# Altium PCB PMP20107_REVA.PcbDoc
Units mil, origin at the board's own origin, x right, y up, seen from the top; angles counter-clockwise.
Board outline 1580 x 1300 mil, 4 copper layers (Top Layer, Signal Layer 1, Signal Layer 2, Bottom Layer), stack 61.2 mil thick; 70 components, 36 nets, 176 pads, 61 vias.
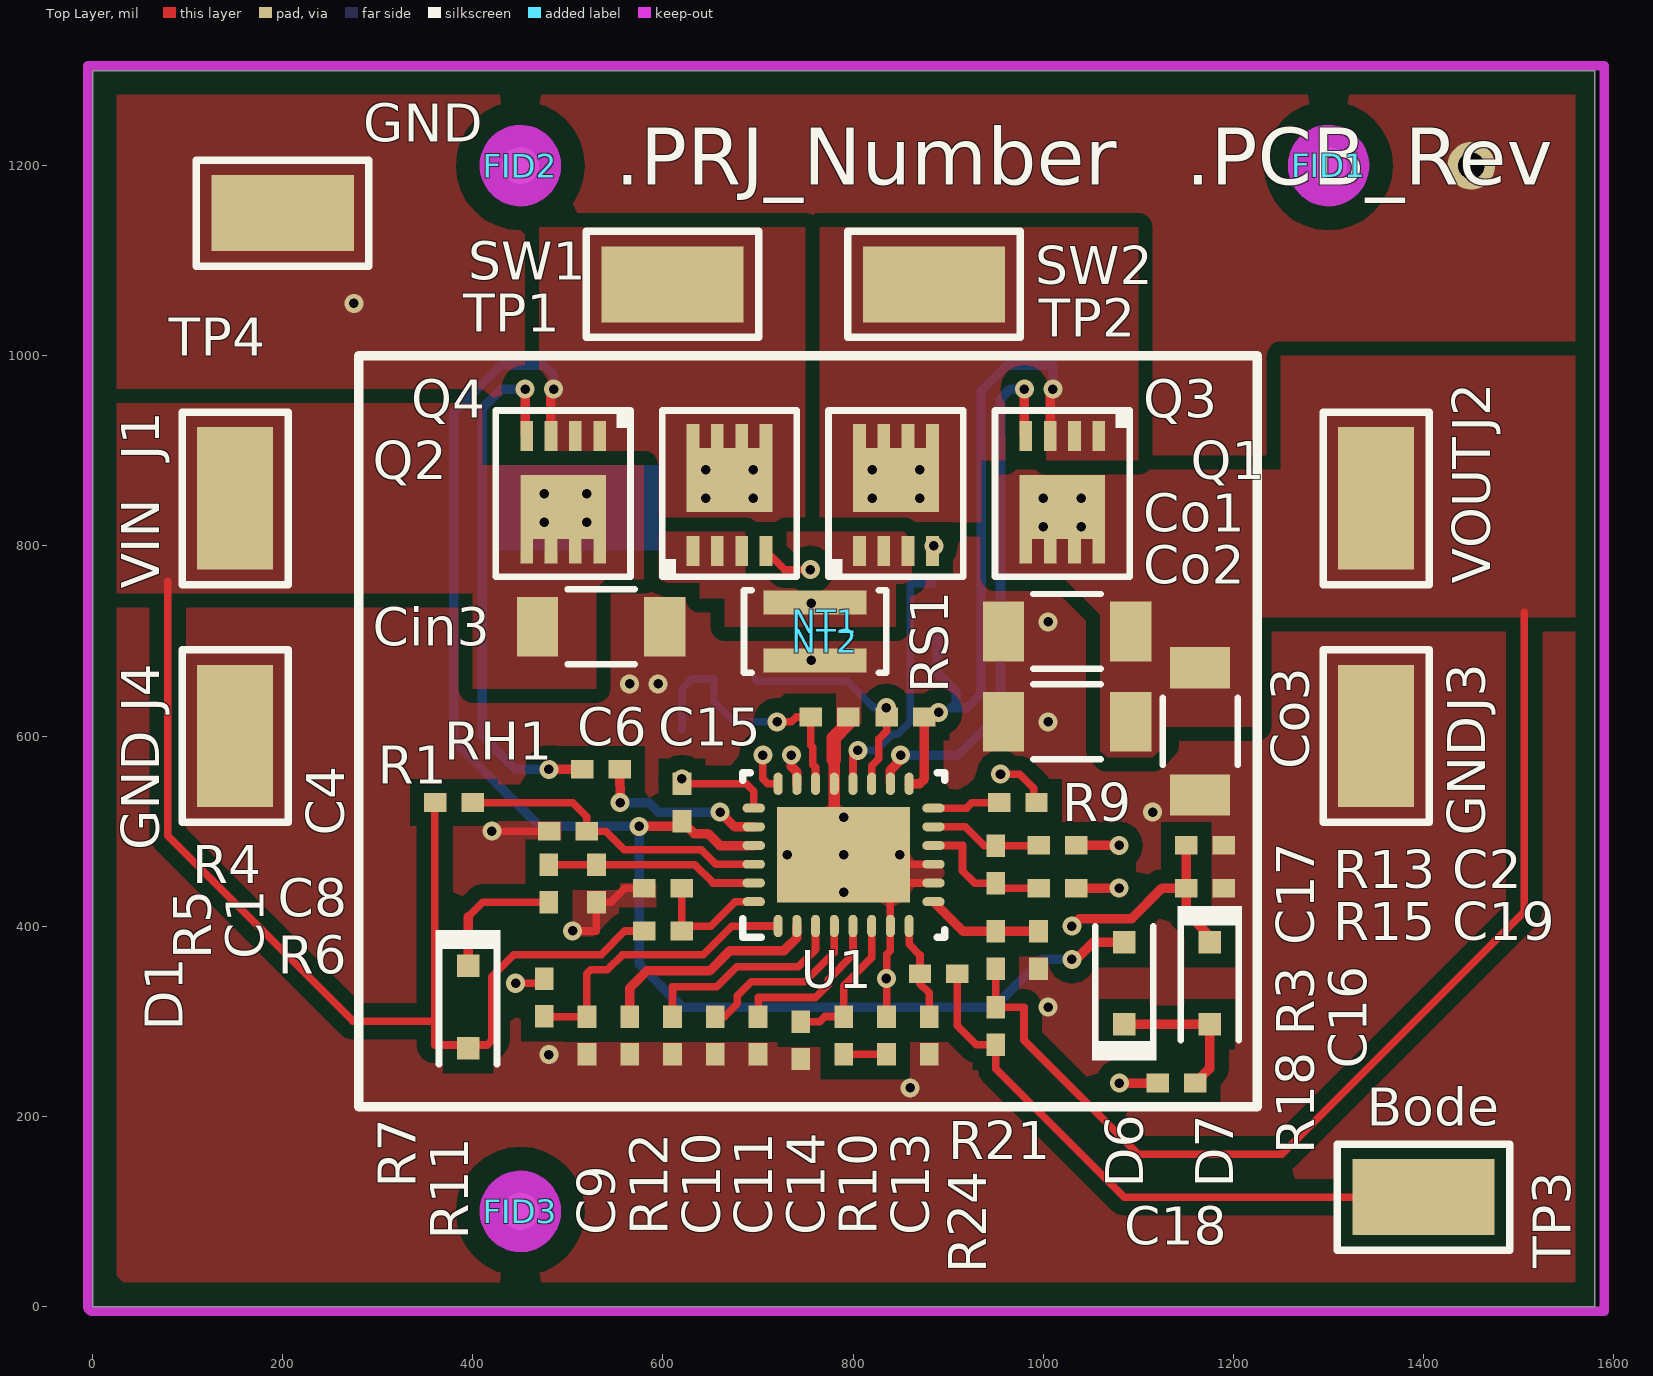
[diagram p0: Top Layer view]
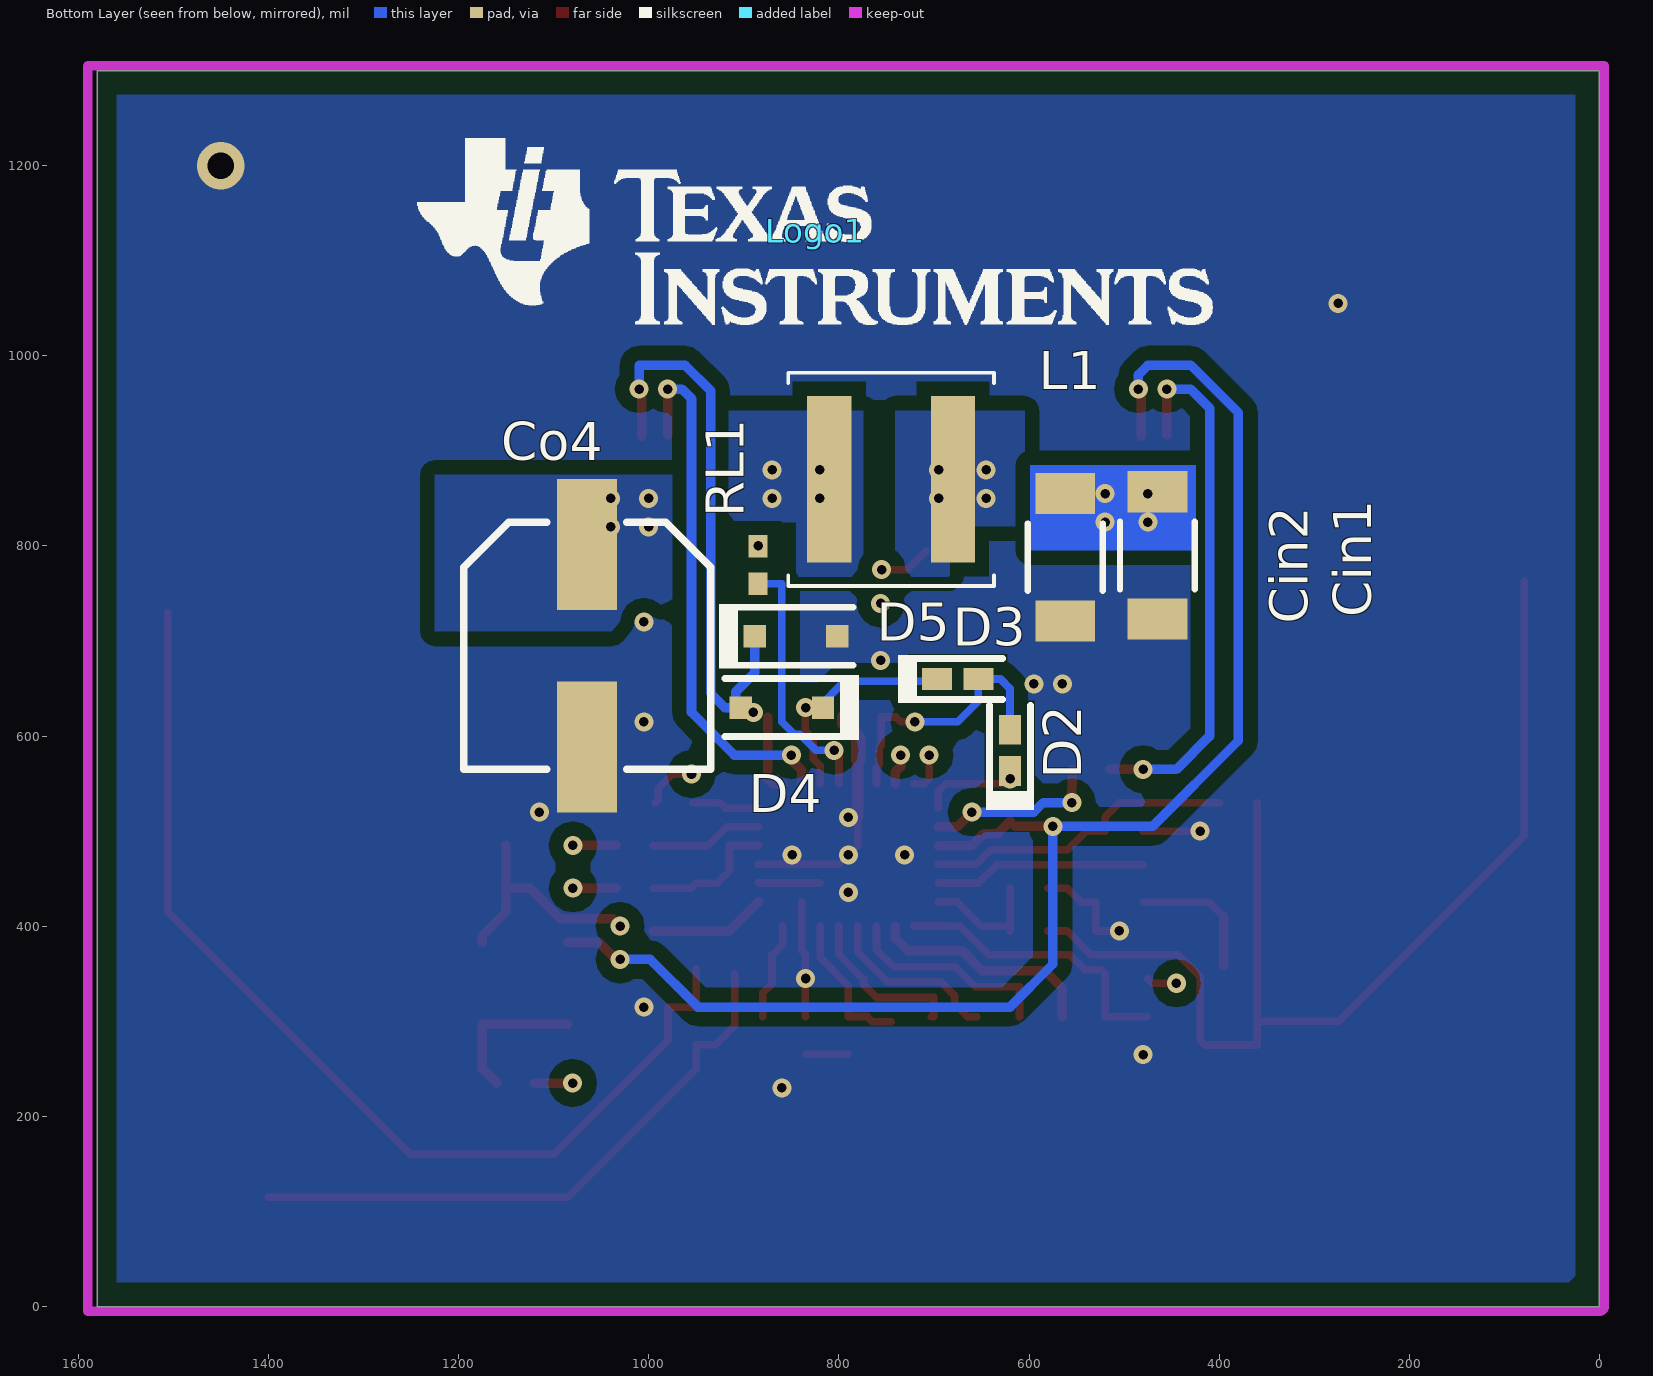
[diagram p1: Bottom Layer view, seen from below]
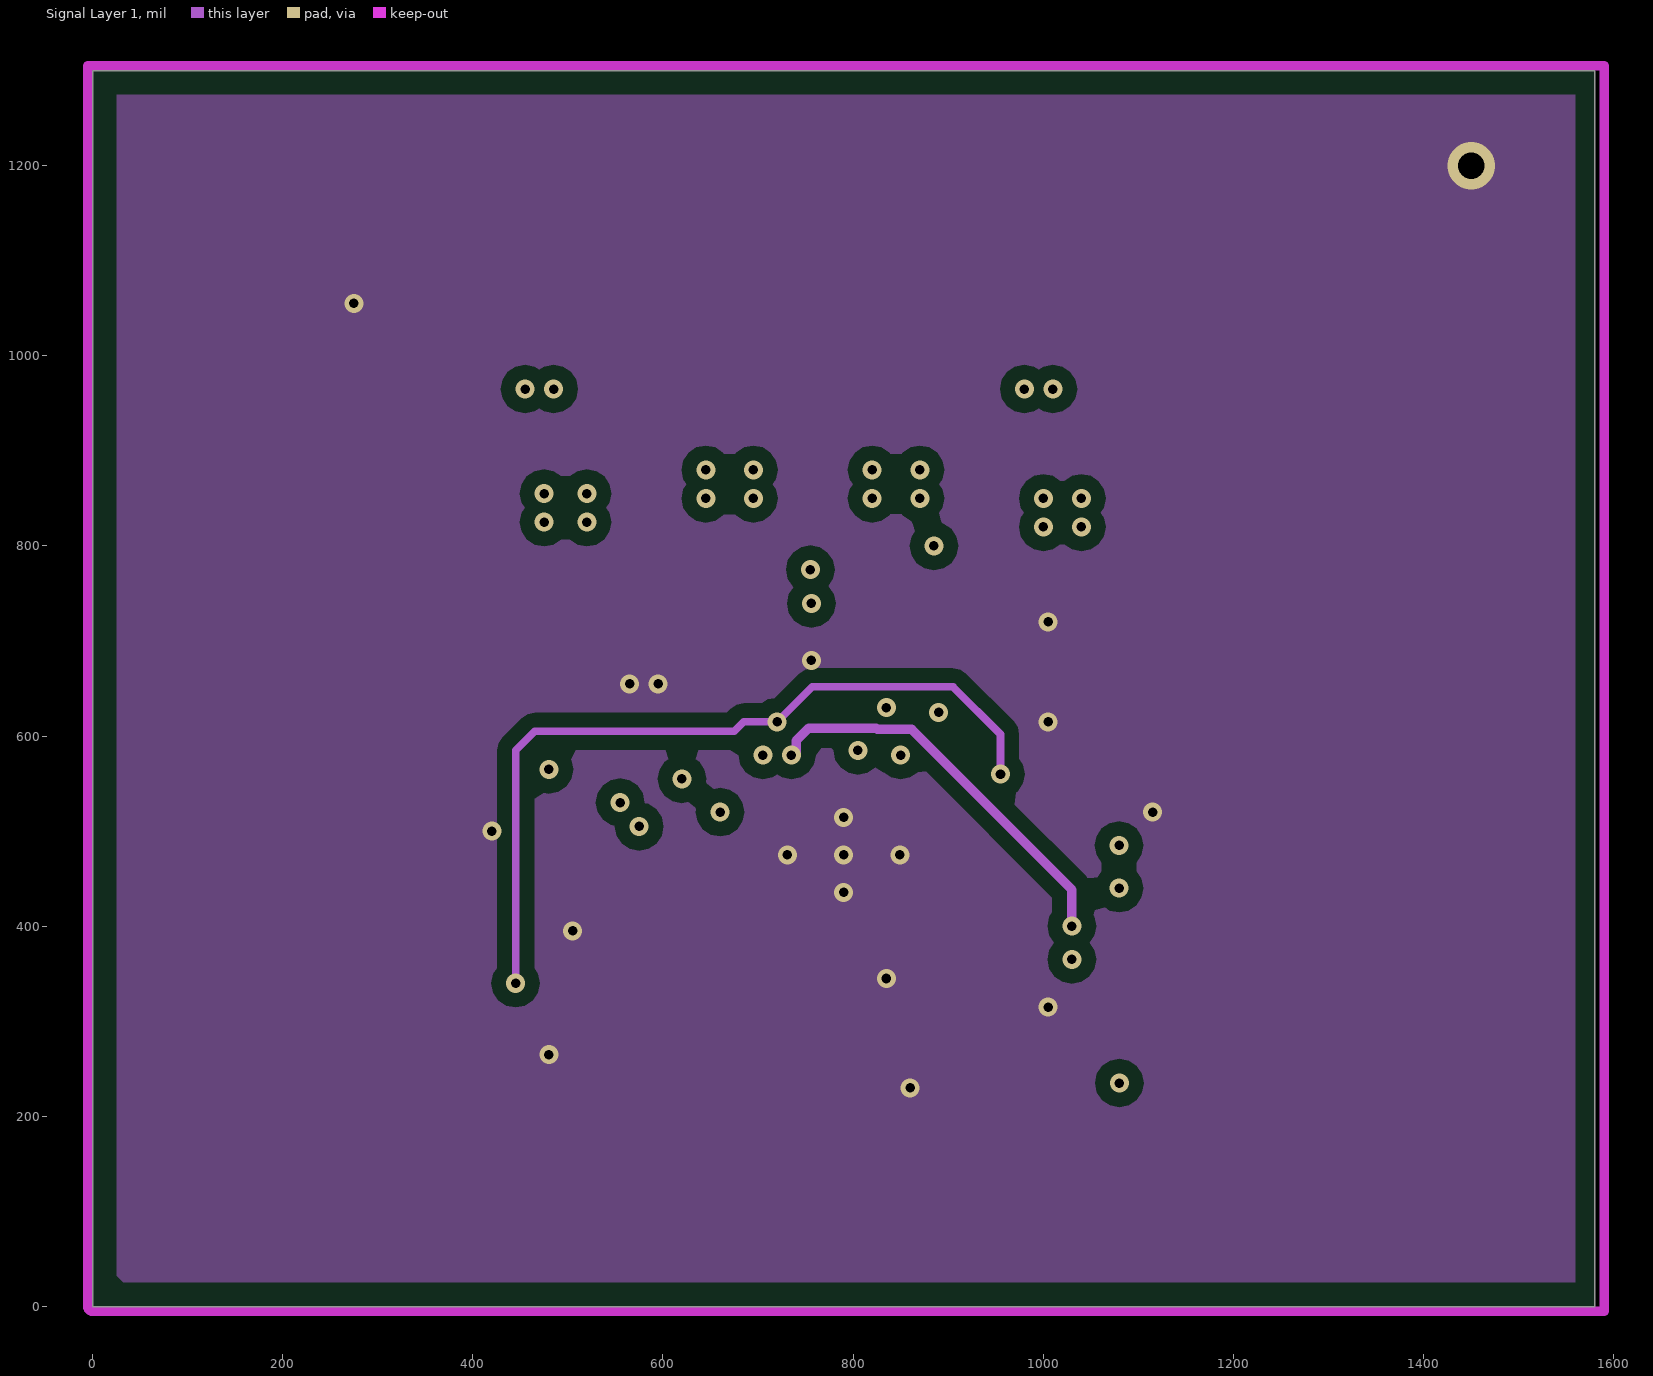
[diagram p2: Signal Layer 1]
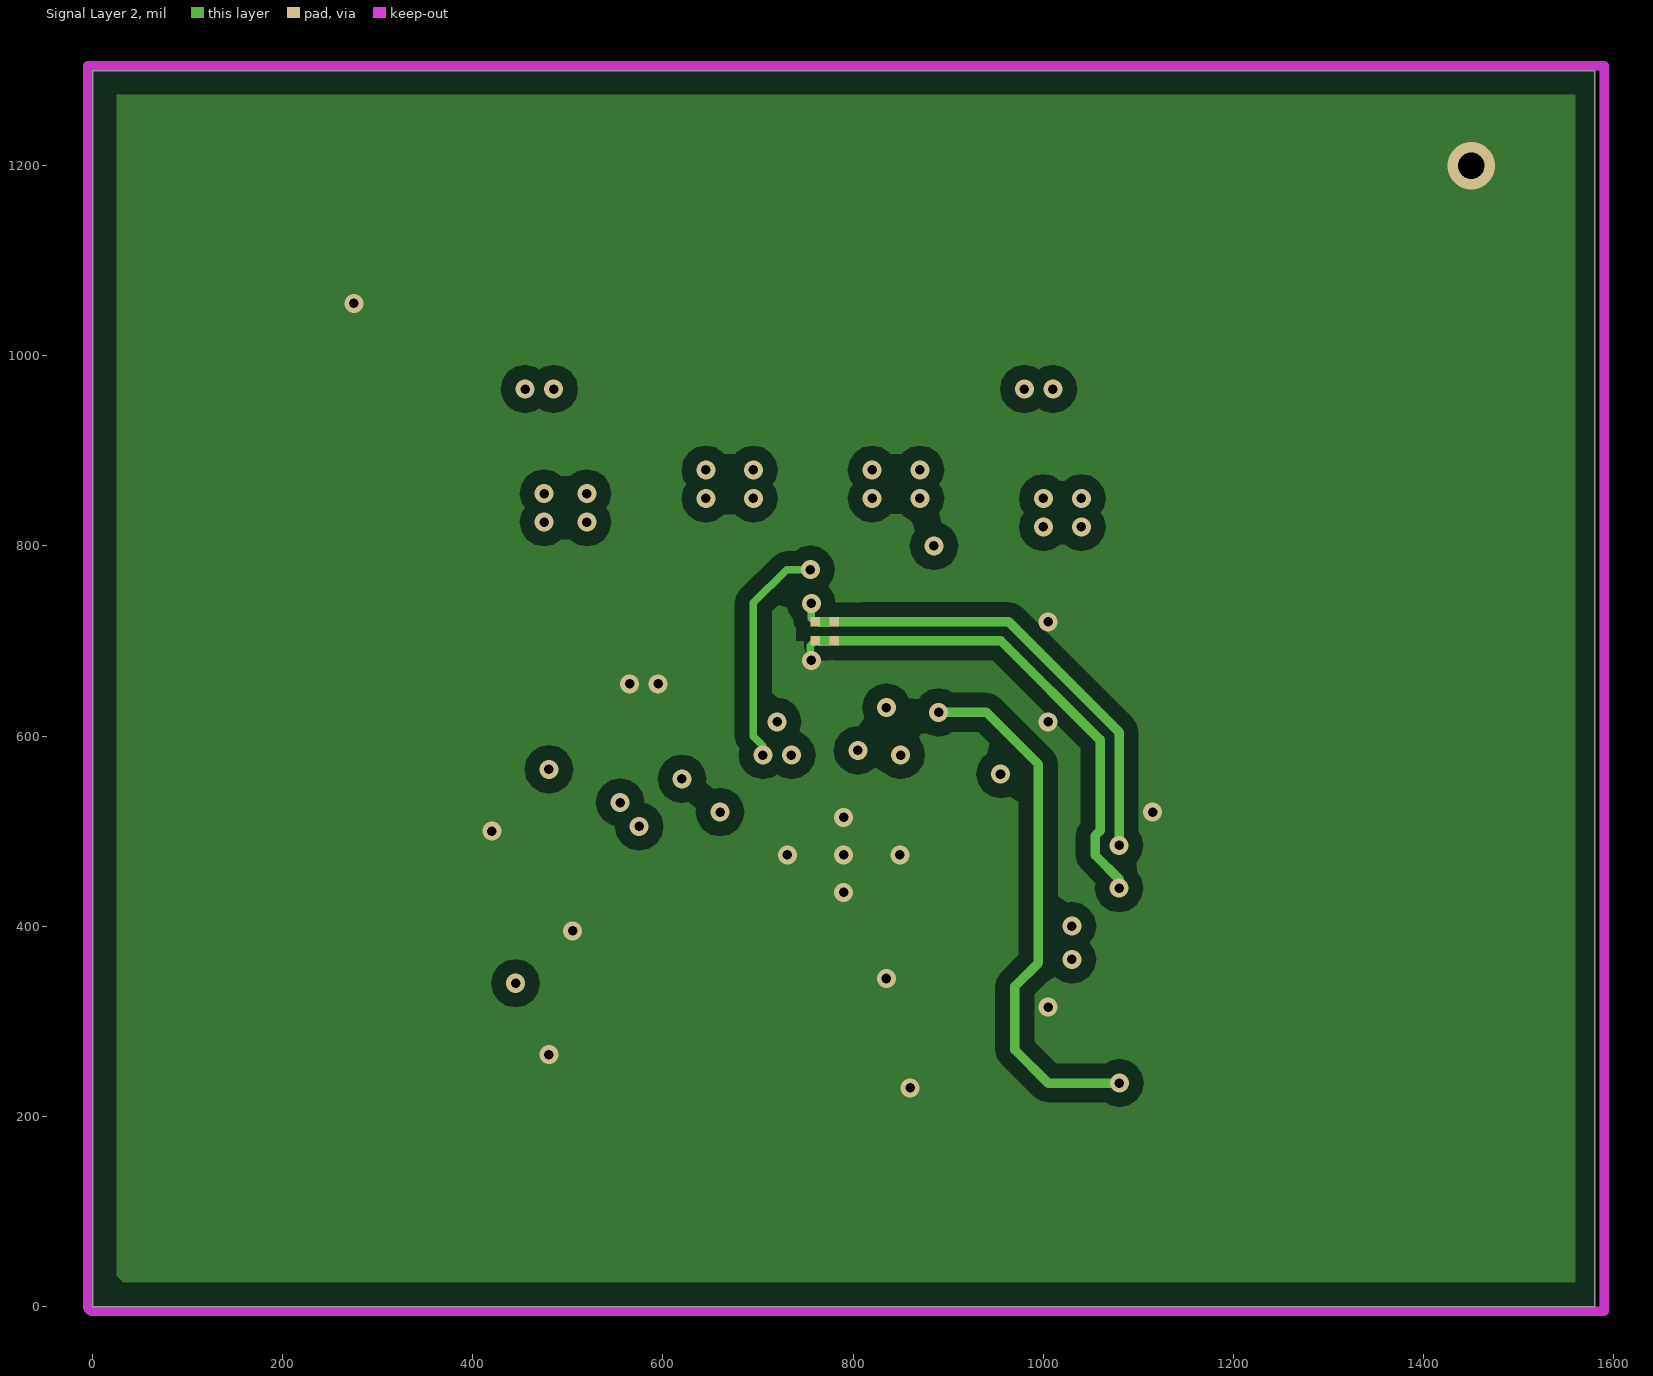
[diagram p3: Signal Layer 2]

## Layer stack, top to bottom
Top Solder: solder mask 0.4, Solder Resist, Dk 3.5
Top Layer: signal copper 1.4
Dielectric1: core 20, FR-4, Dk 4.8
Signal Layer 1: signal copper 0.7
Dielectric 2: prepreg 17, Dk 4.2
Signal Layer 2: signal copper 0.7
Dielectric 3: core 20, FR-4, Dk 4.8
Bottom Layer: signal copper 1.4
Bottom Solder: solder mask 0.4, Solder Resist, Dk 3.5

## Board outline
0,0 1580,0 1580,1300 0,1300

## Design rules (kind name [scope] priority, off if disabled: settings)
AcuteAngle [All] p1: minimum=4.50000000000000E+0001 checktracksonly=FALSE
AssemblyTestPointUsage [All] p1: valid=2
Clearance Clearance_Keepouts [((IsTrack Or IsArc) And Not InPoly) And IsFree and IsKeepOut vs ((IsTrack Or IsArc) And Not InPoly) And IsFree and IsKeepOut] p1: gap=0
Clearance Clearance_BoardEdge_MountingHoles [OnCopper and InComponentClass('Mounting Holes') vs IsKeepOut] p2: gap=40
Clearance Clearance_BoardEdge_Poly [OnCopper and InPoly vs IsKeepOut] p3: gap=25
Clearance Clearance_BoardEdge [OnCopper and Not InComponentClass('Logo') and not InComponentClass('FiducialMark') and not InRegion(1000,500,4000,800) and Not IsKeepout vs IsKeepOut] p4: gap=75
Clearance Clearance_Poly [InPolygon] p5: gap=15
Clearance [All] p6: gap=7.87
ComponentClearance ComponentClearance_Nettie [HasFootprint('Net-Tie_10mil')] p1: gap=0 collisioncheckmode=3 verticalgap=0 showdistances=FALSE
ComponentClearance ComponentClearance_MountingHoles_FiducialMarks [InComponentClass('Mounting Holes') vs InComponentClass('FiducialMark')] p2: gap=50 collisioncheckmode=3 verticalgap=10 showdistances=FALSE
ComponentClearance ComponentClearance_Shunt [InComponentClass('Header') vs InComponentClass('Shunt')] p3: gap=0 collisioncheckmode=3 verticalgap=0 showdistances=FALSE
ComponentClearance ComponentClearance_Logo [InComponentClass('Logo')] p4: gap=50 collisioncheckmode=3 verticalgap=10 showdistances=FALSE
ComponentClearance ComponentClearance_ScrewToNut [(HasFootprint('NY PMS 440 0025 PH')) vs (HasFootprint('Keystone_1902C'))] p5: gap=5 collisioncheckmode=3 verticalgap=10 showdistances=FALSE
ComponentClearance ComponentClearance_MountingHoles [InComponentClass('Mounting Holes')] p6: gap=250 collisioncheckmode=3 verticalgap=100000 showdistances=FALSE
ComponentClearance ComponentClearance_SmallPassives [HasFootprint('0201*') or HasFootprint('0402*') or HasFootprint('0508') or HasFootprint('0603*') or HasFootprint('0612') or HasFootprint('0805*') or HasFootprint('0815*') or HasFootprint('0830*') or HasFootprint('1206*') or HasFootprint('1210*') or HasFootprint('1808*') or HasFootprint('1812*') or HasFootprint('1825*') or HasFootprint('2010*') or HasFootprint('2220*') or HasFootprint('2225*') or HasFootprint('2512*') or HasFootprint('2728*') or HasFootprint('3518*') or HasFootprint('SOD-123') or HasFootprint('SOD-323') vs HasFootprint('0201*') or HasFootprint('0402*') or HasFootprint('0508') or HasFootprint('0603*') or HasFootprint('0612') or HasFootprint('0805*') or HasFootprint('0815*') or HasFootprint('0830*') or HasFootprint('1206*') or HasFootprint('1210*') or HasFootprint('1808*') or HasFootprint('1812*') or HasFootprint('1825*') or HasFootprint('2010*') or HasFootprint('2220*') or HasFootprint('2225*') or HasFootprint('2512*') or HasFootprint('2728*') or HasFootprint('3518*') or HasFootprint('SOD-123') or HasFootprint('SOD-323')] p7: gap=20 collisioncheckmode=3 verticalgap=10 showdistances=FALSE
ComponentClearance ComponentClearance_THtoSMT [IsThruComponent vs IsSMTComponent] p8: gap=100 collisioncheckmode=3 verticalgap=30 showdistances=FALSE
ComponentClearance ComponentClearance_THtoTH [IsThruComponent vs IsThruComponent] p9: gap=100 collisioncheckmode=3 verticalgap=30 showdistances=FALSE
ComponentClearance [All] p10: gap=20 collisioncheckmode=3 verticalgap=10 showdistances=FALSE
DiffPairsRouting [All] p1: maxlimit=100 minlimit=10 mostfreqgap=10 toplayer_minwidth=10 toplayer_maxwidth=15 toplayer_prefwidth=15 midlayer1_minwidth=10 midlayer1_maxwidth=15 midlayer1_prefwidth=15 midlayer2_minwidth=10 midlayer2_maxwidth=15 midlayer2_prefwidth=15 bottomlayer_minwidth=10 bottomlayer_maxwidth=15 bottomlayer_prefwidth=15 maxuncoupledlength=1000
FabricationTestPointUsage TestPointUsage [All] p1: valid=2 allowmultiple=FALSE
FabricationTestpoint Testpoint [All] p1: side=3 testpointundercomponent=TRUE minsize=40 maxsize=100 preferedsize=60 minholesize=0 maxholesize=40 preferedholesize=32 testpointgrid=1 allowsidetop=TRUE allowsidebottom=TRUE usegrid=TRUE gridtolerance=0.01
FanoutControl Fanout_LCC [IsLCC] p1: bgadir=Out bgaviamode=Centered fanoutstyle=Auto fanoutdirection=Alternating viagrid=1 // Fanout_LCC (Default Rule)
FanoutControl Fanout_BGA [IsBGA] p2: bgadir=Out bgaviamode=Centered fanoutstyle=Auto fanoutdirection=Alternating viagrid=1 // Fanout_BGA (Default Rule)
FanoutControl Fanout_Default [All] p4: bgadir=Out bgaviamode=Centered fanoutstyle=Auto fanoutdirection=Alternating viagrid=1 // Fanout_Default (Default Rule)
FanoutControl Fanout_Small [(CompPinCount < 5)] p5: bgadir=Out bgaviamode=Centered fanoutstyle=Auto fanoutdirection=OutThenIn viagrid=1 // Fanout_Small (Default Rule)
HoleSize [All] p1: absolutevalues=TRUE maxlimit=251 minlimit=8 maxpercent=80.000 minpercent=20.000
MinimumAnnularRing MinimumAnnularRing_ThermalPadVias [IsVia and InAnyComponent] p1: minimumring=5
MinimumAnnularRing [All] p2: minimumring=5
MinimumSolderMaskSliver MinimumSolderMaskSliver_Logo [InComponentClass('Logo') vs InComponentClass('Logo')] p1: minsoldermaskwidth=0.7
MinimumSolderMaskSliver [All] p2: minsoldermaskwidth=3.94
PlaneConnect [All] p1: planeconnectstyle=Direct reliefexpansion=10 reliefentries=4 reliefconductorwidth=10 reliefairgap=10
PolygonConnect [All] p1: connectstyle=Direct reliefconductorwidth=10 reliefentries=4 polygonreliefangle="90 Angle" airgapwidth=10
RoutingVias ThermalPadVias [IsVia and InAnyComponent] p1: holewidth=7.87 width=19.68 viastyle="Through Hole" minholewidth=7.87 minwidth=19.68 maxholewidth=12.99 maxwidth=23.62
RoutingVias [All] p2: holewidth=16 width=34 viastyle="Through Hole" minholewidth=7.87 minwidth=20 maxholewidth=40 maxwidth=65
SilkToBoardRegionClearance [Not ((IsComment or IsDesignator) And (Hide <> 'False')) and not InRegion(1000,500,4000,800)] p1:
SilkToSilkClearance SilkToSilkClearance_Pb-FreeLogo [(HasFootprint('Pb-Free_Overlay_Medium') OR HasFootprint('Pb-Free_Overlay_Small')) vs (HasFootprint('Pb-Free_Overlay_Medium') OR HasFootprint('Pb-Free_Overlay_Small'))] p1: silktosilkclearance=0
SilkToSilkClearance [All] p2: silktosilkclearance=4
SilkToSolderMaskClearance SilkToComonentPadClearance [IsPad and InAnycomponent] p1: minsilkscreentomaskgap=5 clearancetoexposedcopper=TRUE
SilkToSolderMaskClearance "Silk to Solder Mask Opening" [All] p2: minsilkscreentomaskgap=4 clearancetoexposedcopper=FALSE
SolderMaskExpansion [All] p1: expansion=1.97
UnpouredPolygon [All] p1: allowunpoured=FALSE
Width [All] p1: maxlimit=100 minlimit=6 preferedwidth=10 checkconnectedcopper=TRUE
14 further rules are at their usual default settings.

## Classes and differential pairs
component class PMP20107_REVA: C1 C2 C4 C6 C8 C9 C10 C11 C13 C14 C15 C16 C17 C18 C19 Cin1 Cin2 Cin3 Co1 Co2 Co3 Co4 Co6 D1 D2 D3 D4 D5 D6 D7 J1 J2 J3 J4 L1 NT1 NT2 Q1 Q2 Q3 Q4 R1 R3 R4 R6 R7 R9 R10 R11 R12 R13 R15 R18 R21 R24 RH1 RL1 RS1 TP1 TP2 TP3 TP4 U1
component class Logo: Logo1
component class PMP20107_REVA_Hardware: FID1 FID2 FID3 Logo1 ZZ1 ZZ2 ZZ3
component class FiducialMark: FID1 FID2 FID3
component class AssemblyNote: ZZ1 ZZ2 ZZ3
differential pair HDRV2: +HDRV2_P -HDRV2_N
differential pair HDRV1: +HDRV1_P -HDRV1_N
differential pair CS: +CS_P -CS_N

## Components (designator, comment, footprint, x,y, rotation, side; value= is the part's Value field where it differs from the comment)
C1 "GCM155R71H104KE02D" 0402L 530,445 r270 top
C2 "C1005X5R1E224M050BC" 0402L 1170,485 r0 top
C4 "GCM155R71H104KE02D" 0402L 620,530 r270 top
C6 "C1005X5R1C105K050BC" 0402L 775,620 r0 top
C8 "GCM155R71H104KE02D" 0402L 600,440 r0 top
C9 "CRCW04020000Z0ED" 0402L 565,285 r270 top
C10 "CC0402KRX7R9BB101" 0402L 655,285 r270 top
C11 "C1005X7R1H473K050BB" 0402L 700,285 r270 top
C13 "GRM155R71E473KA88D" 0402L 835,285 r90 top
C14 "GRM155R71E153KA61D" 0402L 745,280 r270 top
C15 "GCM155R71H104KE02D" 0402L 855,620 r180 top
C16 "C1005X5R1E224M050BC" 0402L 995,375 r270 top
C17 "C1005X7R1H221K" 0402L 950,465 r270 top
C18 "C1005X5R1E224M050BC" 0402L 1140,235 r180 top
C19 "GCM155R71H104KE02D" 0402L 1170,440 r0 top
Cin1 "C3216X7R1V106M160AC" 1206_190 465,790 r270 bottom
Cin2 "C3216X7R1V106M160AC" 1206_190 561.93,788.07 r270 bottom
Cin3 "C3216X7R1V106M160AC" 1206_190 535,715 r0 top
Co1 "GRM31CR71A226ME15L" 1206_190 1025,710 r180 top
Co2 "GRM31CR71A226ME15L" 1206_190 1025,615 r180 top
Co3 "GRM31CR71A226ME15L" 1206_190 1165,605 r270 top
Co4 "UUD1A101MCL1GS" SM_RADIAL_6.3AMM 1065,695 r270 bottom
D1 "BAT54HT1G" sod-323 395,315 r270 top
D2 "BAS516,115" SOD-523 620,585 r90 bottom
D3 "BAS516,115" SOD-523 675,660 r180 bottom
D4 "MMSZ5237BS-7-F" sod-323 860,630 r0 bottom
D5 "CUS05S40,H3F" sod-323 845,705 r180 bottom
D6 "CUS05S40,H3F" sod-323 1085,340 r90 top
D7 "CUS05S40,H3F" sod-323 1175,340 r270 top
FID1 "Fiducial" Fiducial10-20 1300,1200 r0 top
FID2 "Fiducial" Fiducial10-20 450,1200 r0 top
FID3 "Fiducial" Fiducial10-20 450,100 r0 top
J1 "VIN" Keystone_5019 150,850 r90 top
J2 "VOUT" Keystone_5019 1350,850 r90 top
J3 "GND" Keystone_5019 1350,600 r90 top
J4 "GND" Keystone_5019 150,600 r90 top
L1 "XAL5050-562MEB" XAL5050 745,870 r0 bottom
Logo1 "Texas Instruments" TI_Stacked_Overlay_Small 825,1130.71 r180 bottom
NT1 "Net-Tie" Net-Tie_10mil 770,720 r0 top net-tie
NT2 "Net-Tie" Net-Tie_10mil 770,700 r0 top net-tie
Q1 "BSZ097N04LS G" PG-TSDSON-8 1020,855 r270 top
Q2 "BSZ097N04LS G" PG-TSDSON-8 495,855 r270 top
Q3 "BSZ097N04LS G" PG-TSDSON-8 845,855 r90 top
Q4 "BSZ097N04LS G" PG-TSDSON-8 670,855 r90 top
R1 "CRCW040271K5FKED" 0402L 380,530 r180 top
R3 "CRCW040210R0JNED" 0402L 950,375 r270 top
R4 "CRCW040246K4FKED" 0402L 500,500 r0 top
R5 "CRCW040210R0JNED" 0402L 480,445 r270 top
R6 "CRCW040210R0JNED" 0402L 600,395 r0 top
R7 "CRCW04020000Z0ED" 0402L 475,325 r90 top
R9 "CRCW040220K0JNED" 0402L 973.19,530 r0 top
R10 "CRCW04022K49FKED" 0402L 790,285 r90 top
R11 "DNP" 0402L 520,285 r90 top
R12 "CRCW040284K5FKED" 0402L 610,285 r90 top
R13 "CRCW0402100RFKED" 0402L 1015,485 r0 top
R15 "CRCW0402100RFKED" 0402L 1015,440 r0 top
R18 "CRCW040247R0JNED" 0402L 950,295 r270 top
R21 "CRCW040249K9FKED" 0402L 890,350 r0 top
R24 "CRCW04029K53FKED" 0402L 880,285 r90 top
RH1 "CRCW04023R00JNED" 0402L 535,565 r180 top
RL1 "CRCW04020000Z0ED" 0402L 885,780 r270 bottom
RS1 "ERJ-B2CFR01V" 0612 760,710 r90 top
TP1 "SW1" Keystone_5019 610,1075 r0 top
TP2 "SW2" Keystone_5019 885,1075 r0 top
TP3 "Bode" Keystone_5019 1400,115 r0 top
TP4 "GND" Keystone_5019 200,1150 r0 top
U1 "LM5175RHFR" RHF0028A 790,475 r90 top
ZZ1 "These assemblies are ESD sensitive, ESD precautions shall be observed." AssemblyNote 185,3829.11 r0 top
ZZ2 "These assemblies must be clean and free from flux and all contaminants. Use of no clean flux is not acceptable." AssemblyNote 185,3740.56 r0 top
ZZ3 "These assemblies must comply with workmanship standards IPC-A-610 Class 2, unless otherwise specified." AssemblyNote 185,3652 r0 top

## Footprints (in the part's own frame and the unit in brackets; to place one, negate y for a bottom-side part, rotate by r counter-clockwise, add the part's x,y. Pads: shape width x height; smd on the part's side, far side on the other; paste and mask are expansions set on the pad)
0402L [mm] "0402 from SM-752 data"
  rect 0.6x0.5 smd: 1(-0.5,0) 2(0.5,0)
  body extent -0.55,-0.3 0.55,0.3, height 0.6
0612 [mm] "Panasonic recommended land pattern, fb97d03ed01.pdf dated April 2008"
  rect 0.65x2.75 smd: 1(-0.775,0) 2(0.775,0)
  silkscreen extent -1.1,-1.9 1.1,1.9, body extent -0.9,-1.7 0.9,1.7, height 0.85
1206_190 [mm] "1206_190"
  rect 1.1x1.6 smd: 1(-1.7,0) 2(1.7,0)
  silkscreen extent -0.9,-1 0.9,1, body extent -1.75,-0.95 1.75,0.95, height 1.9
AssemblyNote [mil] "Assembly Note"
Fiducial10-20 [mm]
  round 1 smd mask+0.5: 1(0,0)
  Top Layer keep-out circle w1.178: c0,0 r0.5
Keystone_5019 [mm] "Test Point, Miniature, SMT"
  rect 3.8x2.03 smd: 1(0,0)
  silkscreen extent -2.31,-1.42 2.31,1.42, body extent -1.9,-1.02 1.9,1.02, height 2.29
Net-Tie_10mil [mil] "10mil net tie, no solder mask opening, no solder paste"
  rect 10x10 on Mid2 paste-5 mask-5: 1(-10,0) 2(10,0)
  Signal Layer 2 region: -6,5 6,5 6,-5 -6,-5
PG-TSDSON-8 [mm] "Infineon recommended land pattern"
  rect 0.8x0.34 smd: 1(-1.538,0.975) 2(-1.538,0.325) 3(-1.538,-0.325) 4(-1.538,-0.975)
  rect 0.65x0.34 smd: 5(1.538,-0.975) 6(1.538,-0.325) 7(1.538,0.325) 8(1.538,0.975)
  rect 1.71x2.29 smd: 9(0.358,0)
  silkscreen extent -2.22,-1.8 2.22,1.8, body extent -1.7,-1.7 1.7,1.7, height 1.1
RHF0028A [mm] "QFN, 28-Leads, Body 5x4mm, Pitch 0.5mm, Thermal Pad 3.55x2.55mm"
  oval 0.6x0.24 smd: 1(-1.9,1.75) 2(-1.9,1.25) 3(-1.9,0.75) 4(-1.9,0.25) 5(-1.9,-0.25) 6(-1.9,-0.75) 7(-1.9,-1.25) 8(-1.9,-1.75) 15(1.9,-1.75) 16(1.9,-1.25) 17(1.9,-0.75) 18(1.9,-0.25) 19(1.9,0.25) 20(1.9,0.75) 21(1.9,1.25) 22(1.9,1.75)
  oval 0.24x0.6 smd: 9(-1.25,-2.4) 10(-0.75,-2.4) 11(-0.25,-2.4) 12(0.25,-2.4) 13(0.75,-2.4) 14(1.25,-2.4) 23(1.25,2.4) 24(0.75,2.4) 25(0.25,2.4) 26(-0.25,2.4) 27(-0.75,2.4) 28(-1.25,2.4)
  rect 2.55x3.55 smd paste-3.55: 29(0,0)
  silkscreen extent -2.2,-2.7 2.2,2.7, body extent -2.07,-2.57 2.07,2.57, height 1.01
SM_RADIAL_6.3AMM [mm] "Nichicon 6.3x5.8"
  rect 3.5x1.6 smd: 1(-2.7,0) 2(2.7,0)
  silkscreen extent -3.3,-3.29 3.3,3.31, body extent -3.5,-3.3 3.5,3.3, height 6.11
sod-323 [mm] "NXP recommended land pattern"
  rect 0.6x0.6 smd paste-0.05: 1(-1.1,0) 2(1.1,0)
  silkscreen extent -2.06,-0.86 1.53,0.86, body extent -1.3,-0.67 1.3,0.68, height 1.1
SOD-523 [mm] "NXP Semiconductor recommended land pattern, nominal STEP model"
  rect 0.8x0.6 smd paste-0.05: 1(-0.55,0) 2(0.55,0)
  silkscreen extent -1.6,-0.63 1.2,0.64, body extent -0.8,-0.4 0.8,0.4, height 0.72
TI_Stacked_Overlay_Small [mil]
  silkscreen extent -418,-98 418,98
XAL5050 [mm] "CoilCraft XAL5050 5.28 x 5.48 x 5.1 mm"
  rect 1.18x4.44 smd: 1(-1.655,0) 2(1.655,0)
  silkscreen extent -2.75,-2.85 2.75,2.85, body extent -2.74,-2.84 2.74,2.84, height 5.1

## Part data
C1 C4 C8 C15 C19: "CAP, CERM, 0.1 µF, 50 V, +/- 10%, X7R, AEC-Q200 Grade 1, 0402"
C2 C16 C18: "CAP, CERM, 0.22 µF, 25 V, +/- 20%, X5R, 0402"
C6: "CAP, CERM, 1 µF, 16 V, +/- 10%, X5R, 0402"
C9 R7 RL1: "RES, 0, 5%, 0.063 W, 0402"
C10: "CAP, CERM, 100 pF, 50 V, +/- 10%, X7R, 0402"
C11: "CAP, CERM, 0.047 µF, 50 V, +/- 10%, X7R, 0402"
C13: "CAP, CERM, 0.047 µF, 25 V, +/- 10%, X7R, 0402"
C14: "CAP, CERM, 0.015 µF, 25 V, +/- 10%, X7R, 0402"
C17: "CAP, CERM, 220 pF, 50 V, +/- 10%, X7R, 0402"
Cin1 Cin2 Cin3: "CAP, CERM, 10 µF, 35 V, +/- 20%, X7R, 1206_190"
Co1 Co2 Co3: "CAP, CERM, 22 µF, 10 V, +/- 20%, X7R, 1206_190"
Co4: "CAP, AL, 100 µF, 10 V, +/- 20%, 0.44 ohm, SMD"
D1: "Diode, Schottky, 30V, 0.2A, SOD-323"
D2 D3: "Diode, Switching, 100V, 0.25A, SOD-523"
D4: "Diode, Zener, 8.2 V, 200 mW, SOD-323"
D5 D6 D7: "Diode, Schottky, 40 V, 0.5 A, SOD-323"
FID1 FID2 FID3: "Fiducial mark.  There is nothing to buy or mount."
J1 J2 J3 J4 TP1 TP2 TP3 TP4: library part 5019, "Test Point, Miniature, SMT"
L1: "Inductor, Shielded, Composite, 5.6 µH, 6.3 A, 0.03 ohm, SMD"
Logo1: library part TI_Logo, "Texas Instrument Corporate Signature"
NT1 NT2: "Single point connection between nets."
Q1 Q2 Q3 Q4: "MOSFET, N-CH, 40 V, 40 A, PG-TSDSON-8"
R1: "RES, 71.5 k, 1%, 0.063 W, 0402"
R3 R5 R6: "RES, 10, 5%, 0.063 W, 0402"
R4: "RES, 46.4 k, 1%, 0.063 W, 0402"
R9: "RES, 20 k, 5%, 0.063 W, 0402"
R10: "RES, 2.49 k, 1%, 0.063 W, 0402"
R11: library part CRCW040295K3FKED, "RES, 95.3 k, 1%, 0.063 W, 0402"
R12: "RES, 84.5 k, 1%, 0.063 W, 0402"
R13 R15: "RES, 100, 1%, 0.063 W, 0402"
R18: "RES, 47, 5%, 0.063 W, 0402"
R21: "RES, 49.9 k, 1%, 0.063 W, 0402"
R24: "RES, 9.53 k, 1%, 0.063 W, 0402"
RH1: "RES, 3.0, 5%, 0.063 W, 0402"
RS1: "RES, 0.01, 1%, 1 W, AEC-Q200 Grade 0, 0612"
U1: "42-V Wide VIN Synchronous 4-Switch Buck-Boost Controller, RHF0028A"
ZZ1 ZZ2 ZZ3: library part AssemblyNote

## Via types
v1: diameter 20, hole 10, Top Layer to Bottom Layer, 60 vias
v2: diameter 50, hole 28, Top Layer to Bottom Layer, 1 vias

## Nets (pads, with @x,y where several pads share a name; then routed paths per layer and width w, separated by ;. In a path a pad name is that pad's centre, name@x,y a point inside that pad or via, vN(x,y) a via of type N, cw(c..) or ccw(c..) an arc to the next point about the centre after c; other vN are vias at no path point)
BIAS: C2.1 C19.1 D7.1 U1.21 | length 700.7
  Top Layer w10: v1(735,580) 735,567.88 740.79,562.09 U1.21 ; v1(1030,400) 1037.99,407.99 1092.99,407.99 1125,440 C19.1 ; C2.1 C19.1 ; D7.1 1175,390 1150.32,414.68 C19.1
  Signal Layer 1 w10: v1@740,580 740,595 753.19,608.19 824.46,608.19 825.53,607.13 861.45,607.13 1030,438.58 v1(1030,400)
BOOT1: C4.1 D2.1 U1.23 | length 97.2
  Top Layer w8: C4.1 687.76,549.68 695.51,541.93 U1.23 U1.23@695,524.72
  other v1: 620,555
BOOT2: C15.2 D3.1 D4.1 U1.17 | length 227.5
  Top Layer w8: U1.17 819.53,568.59 826.87,575.94 826.87,596.87 835.31,605.31 C15.2
  Bottom Layer w8: D3.1 699.04,657.61 794.08,657.61 821.69,630 v1(835,630)
COMP: C14.1 R10.2 U1.6 | length 155.1
  Top Layer w8: C14.1 764.68,299.68 770,305 789.69,305 R10.2 790,337.55 819.53,367.08 U1.6
CS_N: NT2.2 R15.2 | length 536.3
  Top Layer w10: R15.2@1034.37,440 R15.2 v1(1079.68,440)
  Signal Layer 2 w10: NT2.2 798.22,700 ; 798.52,700.3 955.26,700.3 1059.68,595.87 1059.68,500.36 1054.68,495.36 1054.68,474.64 1079.68,449.64 v1(1079.68,440)
CS_P: NT1.2 R13.2 | length 512
  Top Layer w10: R13.2@1034.37,485 R13.2 v1(1079.68,485)
  Signal Layer 2 w10: NT1.2 808.81,720 ; 809.11,720.3 963.54,720.3 1079.68,604.15 v1(1079.68,485)
EN: R1.1 R4.2 U1.26 | length 331.7
  Top Layer w8: R1.1 505,530 519.69,515.31 R4.2 540,500 559.44,480.56 640.02,480.56 655.42,465.16 U1.26
FB: R21.1 R24.2 U1.8 | length 104.3
  Top Layer w8: U1.8 858.9,381.1 870.32,369.68 R21.1 870.32,339.68 880,330 R24.2
GND: C1.2 C2.2 C6.2 C8.1 C9.2 C10.2 C11.2 C13.2 C14.2 C16.2 C19.2 Cin1.2 Cin2.2 Cin3.2 Co1.2 Co2.2 Co3.2 Co4.2 D5.2 J3.1 J4.1 NT2.1 R4.1 R11.1 R12.1 R24.1 RS1.1 TP4.1 U1.7 U1.10 U1.11 U1.19 U1.29 | length 609.1
  Top Layer w8: v1(420,500) R4.1 ; v1(505,395) 530,395 C1.2 545.31,425.31 560,440 C8.1 ; U1.29@780.16,484.84 U1.29@780.16,515 ; U1.29@799.84,465.16 U1.11 ; U1.29@819.53,445.47 U1.10 ; C13.2 835.4,305.09 835.4,370.4 839.21,374.21 U1.7 U1.29@839.21,425.79
  Top Layer w12: 779.63,575.43 780.16,574.9 U1.19 U1.29@780.16,515
  Top Layer w15: 779.63,575.43 779.63,598.04 794.69,613.1 C6.2
  Signal Layer 2 w8: v1(756,679.49) 755,680.49 755,695 NT2.1
  other v1: 860,230 480,265 1005,315 835,345 790,435.63 730.94,475 790,475 849.06,475 790,514.37 1115,520 1005,615 565,655 595,655 1005,720 275,1055
  other v2: 1450,1200
HDRV1_N: C4.2 D6.2 L1.1 Q2.1 Q2.2 Q2.3 Q4.5 Q4.6 Q4.7 Q4.8 Q4.9 TP1.1 U1.25 | length 1596.6
  Top Layer w10: Q2.3 v1@482.2,962.2 ; v1(575,505) C4.2@614.69,505 ; C4.2 632.88,497.43 647.21,497.43 659.8,484.84 U1.25 ; v1(1030,365) 1034.5,365 1052.81,383.31 D6.2
  Bottom Layer w10: v1(485,965) 485,980 475,990 429.72,990 380,940.28 380,595 470,505 v1(575,505) 575,360 620,315 948.35,315 998.35,365 v1(1030,365)
  other v1: 645,850 695,850 645,880 695,880
HDRV1_P: RH1.1 U1.24 | length 186.1
  Top Layer w10: RH1.1 v1(555,530) ; v1(660,520) 675.47,504.53 U1.24
  Bottom Layer w10: v1(555,530) 585,530 595,520 v1(660,520)
HDRV2_N: C15.1 C18.2 D4.2 D5.1 L1.2 Q1.1 Q1.2 Q1.3 Q3.5 Q3.6 Q3.7 Q3.8 Q3.9 TP2.1 U1.15 | length 1283.5
  Top Layer w10: U1.15 869.8,549.8 875,555 875,619.68 C15.1 ; Q1.3 v1@1007.2,962.2 ; v1(1080,235) C18.2
  Signal Layer 2 w10: v1(890,625) 940.2,625 994.82,570.37 994.82,361.48 970,336.65 970,270 1005,235 v1(1080,235)
  Bottom Layer w10: D5.1 888.31,666.69 908.31,646.69 D4.2@908.31,630 ; D4.2 D4.2@908.31,630 ; v1(1010,965) 1010,990 961.72,990 935,963.28 935,645 920,630 D4.2@908.31,630
  other v1: 820,850 870.24,850 820,880 870.24,880
HDRV2_P: Q1.4 U1.16 | length 565.3
  Top Layer w10: U1.16 839.21,564.21 850,575 v1(850,580) ; Q1.4@980,917.15 v1(980,965)
  Bottom Layer w10: v1(850,580) 910,580 955,625 955,955 965,965 v1(980,965)
LDRV1: Q4.4 U1.22 | length 336.6
  Top Layer w8: v1(705,580) 705,555 710.2,549.8 U1.22 ; Q4.4 727.85,775 v1(755,775)
  Signal Layer 2 w8: v1(705,580) 705,590 695,600 695,740 730,775 v1(755,775)
LDRV2: RL1.2 U1.18 | length 274.9
  Top Layer w8: U1.18 799.84,579.84 v1(805,585)
  Bottom Layer w8: v1(805,585) 824.07,585 840.94,601.87 846.87,601.87 860,615 860,760 884.69,760 RL1.2
MODE: R7.1 R11.2 U1.1 | length 311.6
  Top Layer w8: R7.1@475.63,304.69 R11.2 520,350 524.13,354.13 541.58,354.13 557.45,370 642.45,370 672.45,400 688.62,400 688.82,400.2 U1.1
NetC9_1: C9.1 U1.2 | length 240.3
  Top Layer w10: C9.1 565,335 583.13,353.13 649.44,353.13 670.66,374.34 727.22,374.34 740.79,387.91 U1.2
NetC13_1: C13.1 R10.1 | length 45
  Top Layer w8: R10.1 C13.1
NetC17_1: C17.1 R13.1 U1.13 | length 119.2
  Top Layer w8: U1.13 917.92,504.53 937.76,484.68 C17.1 995,484.68 R13.1
NetC17_2: C17.2 R15.1 U1.12 | length 144.9
  Top Layer w8: U1.12 914.84,484.84 915,485 915,458.17 928.17,445 950.31,445 955.31,440 R15.1@995,440
NetC18_1: C18.1 D6.1 D7.2 | length 158
  Top Layer w10: D6.1 D7.2 1175,250.32 C18.1
NetD1_1: D1.1 R5.2 | length 143
  Top Layer w8: 395,410 410.31,425.31 R5.2
  Top Layer w10: D1.1 395,410
NetQ2_4: Q2.4 RH1.2 | length 566
  Top Layer w10: Q2.4@455,917.15 v1(455,965) ; v1(480,565) RH1.2
  Bottom Layer w10: v1(455,965) 430,965 410,945 410,600 445,565 v1(480,565)
NetQ3_4: Q3.4 RL1.1
  other v1: 885,800
NetR18_2: R18.2 R21.2 TP3.1 | length 634.5
  Top Layer w8: R21.2 909.69,295.31 929.69,275.31 R18.2 950,250 1085,115 TP3.1
PGOOD: R9.1 U1.14 | length 71.4
  Top Layer w8: U1.14 919.21,524.21 925,530 R9.1
SLOPE: C10.1 U1.4 | length 185.9
  Top Layer w8: C10.1 664.68,304.68 678.28,318.28 678.28,326.94 692.94,341.6 749.04,341.6 780.16,372.71 U1.4
SS: C11.1 U1.5 | length 175
  Top Layer w8: C11.1@703.01,304.68 C11.1 700,325 760,325 774.13,339.13 774.13,344.13 799.84,369.84 U1.5
SYNC: R12.2 U1.3 | length 223
  Top Layer w8: R12.2 610,336.25 656.43,336.25 677.65,357.47 742.47,357.47 760.47,375.47 U1.3
VCC: C6.1 D2.2 D3.2 R7.2 R9.2 U1.20 | length 1224.2
  Top Layer w8: v1(445,340) 470.31,340 R7.2 ; v1(720,615) 735,615 740,620 C6.1 755.32,590.62 757.66,588.27 757.66,570 760.47,567.19 U1.20 ; v1(955,560) 975,560 990.04,544.96 990.04,532.84 R9.2
  Signal Layer 1 w8: v1(445,340) 445,585 465,605 675,605 685,615 v1(720,615) 756.87,651.87 905,651.87 955,601.87 v1(955,560)
  Bottom Layer w8: D2.2 620,650 630,660 D3.2 653.35,636.65 675,615 v1(720,615)
VIN: Cin1.1 Cin2.1 Cin3.1 D1.2 J1.1 Q2.5 Q2.6 Q2.7 Q2.8 Q2.9 R1.2 R6.1 | length 1194.2
  Top Layer w8: 79,763 79,495 274,300 360,300 ; R1.2 360,529.69 360,300 ; R6.1 560,395 535,370 443,370 420,347 420,280 415,275 360,275 360,300
  other v1: 475,825 520,825 475,855 520,855
VIN_IC: C1.1 R5.1 U1.27 | length 223.5
  Top Layer w8: R5.1 C1.1 633.45,464.68 652.66,445.47 U1.27
VINSNS: C8.2 R6.2 U1.28 | length 131.5
  Top Layer w8: R6.2 C8.2 ; R6.2@619.69,400 650,400 675.79,425.79 U1.28
VOSNS: C16.1 R3.1 U1.9 | length 123.4
  Top Layer w10: U1.9 915.59,394.68 R3.1 C16.1
VOUT: Co1.1 Co2.1 Co3.1 Co4.1 J2.1 Q1.5 Q1.6 Q1.7 Q1.8 Q1.9 R3.2 R18.1 | length 1101.5
  Top Layer w8: R3.2 R18.1 979.68,314.68 979.68,280.32 1100,160 1251,160 1506,415 1506,730
  other v1: 1000,820 1040,820 1000,850 1040,850
VRS: NT1.1 Q3.1 Q3.2 Q3.3 Q4.1 Q4.2 Q4.3 RS1.2 | length 21.2
  Signal Layer 2 w8: v1(756,739.53) 756,724 NT1.1
pads on no net: FID1.1 FID2.1 FID3.1

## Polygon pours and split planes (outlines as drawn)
VIN on Top Layer "Top Layer-Vin" (solid, remove dead copper, pour order 13): 0,950 0,755 0,750 400,750 400,650 530,650 530,755 540,765 580,765 580,885 410,885 410,945 405,950 0,950
GND on Top Layer "Bottom Layer-GND" (solid, remove dead copper, pour order 21): 0,1300 0,0 1580,0 1580,1300 0,1300
VOUT on Top Layer "Top Layer-Vout" (solid, remove dead copper, pour order 17): 949.13,880 949.13,767.6 1020,767.6 1060,727.6 1060,577.62 1115.22,577.62 1127.6,590 1127.6,610 1225,610 1225,725 1580,725 1580,1000 1250,1000 1250,880 940,880
HDRV1_N on Top Layer "Top Layer-HDRV1N" (solid, remove dead copper, pour order 16): 470,1135 470,895 585,895 585,815 760,815 755,820 755,1135 470,1135
HDRV2_N on Top Layer "Top Layer-HDRV2N" (solid, remove dead copper, pour order 15): 765,1135 765,825 935,825 935,890 1100,890 1100,1135 765,1135
VRS on Top Layer "Top Layer-VRS" (solid, remove dead copper, pour order 14): 595,815 595,747.42 595.04,747.38 597.42,745 665,745 665,715 845,715 845,760 871.22,760 871.22,815 595,815
GND on Bottom Layer "Top Layer-GND" (solid, remove dead copper, pour order 23): 0,1300 0,0 1580,0 1580,1300 0,1300
VOUT on Bottom Layer "Bottom Layer-Vout" (solid, remove dead copper, pour order 20): 965.77,875.87 965.77,754.23 980,740 990,730 990,710 1225,710 1225,875 966.64,875
HDRV2_N on Bottom Layer "Bottom Layer-HDRV2N" (solid, remove dead copper, pour order 19): 774.13,942.4 774.13,767.6 845,767.6 845,825 915.87,825 915.87,942.4 774.13,942.4
HDRV1_N on Bottom Layer "Bottom Layer-HDRV1N" (solid, remove dead copper, pour order 18): 605,942.4 604.37,941.77 604.37,820.43 679.57,820.43 680,820 683.23,816.77 683.23,770.5 683.23,769.37 685,767.6 740.87,767.6 740.87,942.4 605,942.4
GND on Signal Layer 1 "Top Layer-GND" (solid, remove dead copper, pour order 22): 0,1295 0,0 1580,0 1580,1300 0,1300
GND on Signal Layer 2 "Signal Layer 2-GND" (solid, remove dead copper, pour order 24): 0,1300 0,0 1580,0 1580,1295 5,1295 0,1300

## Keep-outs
Keep-Out Layer:
  lines w10: -5,0 ccw(c0,0) 0,-5 ; -5,0 ccw(c0,0) 0,-5 ; -5,0 -5,1305 1590,1305 1590,-5 0,-5 ; -5,3450 cw(c0,3450) 0,3455 ccw(c0,3450) -5,3450 ; 4950,-5 ccw(c4950,0) 4955,0 cw(c4950,0) 4950,-5 ; 4950,3455 cw(c4950,3450) 4955,3450 ccw(c4950,3450) 4950,3455
  text ".Layer_Name" at 577,-858.49 h60

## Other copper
Top Layer:
  text ".Layer_Name" at 577,-858.49 h60
Bottom Layer:
  rectangle net VIN: 424.13,795 599.13,885
  text ".Layer_Name" at 577,-858.49 h60

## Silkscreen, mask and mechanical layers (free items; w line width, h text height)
Top Overlay:
  lines w10: 280,210 1225,210 1225,1000 280,1000 280,210
  text ".PRJ_Number" at 550,1180 h60
  text ".PCB_Rev" at 1150,1180 h60
  text ".Layer_Name" at 577,-858.49 h60
Bottom Overlay:
  text ".Layer_Name" at 577,-858.49 h60
Top Paste:
  text ".Layer_Name" at 577,-858.49 h60
Bottom Paste:
  text ".Layer_Name" at 577,-858.49 h60
Top Solder:
  text ".Layer_Name" at 577,-858.49 h60
  text ".Layer_Name" at 577,-858.49 h60
Bottom Solder:
  text ".Layer_Name" at 577,-858.49 h60
Drill Guide:
  text ".Layer_Name" at 577,-858.49 h60
M1 Board Outline:
  the board outline again, w10
  text ".Layer_Name" at 577,-858.49 h60
M2 Board Dimensions:
  rectangle: 0,-275 125,-150
  rectangle: 125,-400 500,-275
  lines w7: 0,-275 1000,-275 ; 125,-400 125,-150 ; 250,-400 250,-150 ; 500,-400 500,-150 ; 750,-400 750,-150 ; 0,-400 1000,-400 1000,-150 0,-150 0,-400
  text ".Layer_Name" at 577,-858.49 h60
M3 3D STEP Top:
  text ".Layer_Name" at 577,-858.49 h60
M4 3D STEP Bottom:
  text ".Layer_Name" at 577,-858.49 h60
M5 Assembly Top:
  lines w10: -292,-930.17 6308,-930.17 ; -292,-726.83 6310,-726.83 ; -292,-523.5 -292,-1133.5 3713,-1133.5 6310,-1133.5 6310,-523.5 -291.5,-523.5 -291.5,-1133.5 1284,-1133.5 ; 2173,-1133.5 2173,-523.5 ; 3440,-726.83 3440,-523.5 ; 4280,-726.83 4280,-523.5 ; 4902,-1140 4902,-937.17
  text "COMPONENTS MARKED 'DNP' SHOULD NOT BE POPULATED." at 1153.5,-318.5 h60
  text "ASSEMBLY VARIANT:" at 1153,-434 h60
  text ".VariantName" at 2189,-434 h60
  text "PCB VIEWED FROM TOP SIDE" at -228.5,-655.67 h60
  text "BOARD #:" at 2248,-655.67 h60
  text ".PRJ_Number" at 2793.5,-655.67 h60
  text "REV:" at 3638,-655.67 h60
  text ".PCB_Rev" at 3929.5,-655.67 h60
  text "SVN REV:" at 4476,-655.67 h60
  text ".VersionControl_RevNumber" at 4982,-655.67 h60
  text "TID #:" at 2248,-859 h60
  text ".TID" at 2793.5,-859 h60
  text "PLOT NAME =" at -228.5,-1064.34 h60
  text ".plot_File_Name" at 577,-1064.34 h60
  text "GENERATED    :" at 2250,-1064.34 h60
  text ".Print_Date" at 3119.5,-1064.34 h60
  text ".Print_Time" at 3848.5,-1064.34 h60
  text "TEXAS INSTRUMENTS" at 5113,-1064.34 h60
M6 Assembly Bottom:
  lines w10: -292.5,-727.33 6309.5,-727.33 ; -290.5,-930.67 6309.5,-930.67 ; 1115.5,-1140.5 1115.5,-937.67 ; 1737.5,-727.33 1737.5,-524 ; 2577.5,-727.33 2577.5,-524 ; 3844.5,-1134 3844.5,-524 ; 4733.5,-1134 6309,-1134 6309,-524 -292.5,-524 -292.5,-1134 2304.5,-1134 6309.5,-1134 6309.5,-524
  text "COMPONENTS MARKED 'DNP' SHOULD NOT BE POPULATED." at 6102,-318 h60
  text ".VariantName" at 5058,-434 h60
  text "ASSEMBLY VARIANT:" at 6097,-434 h60
  text ".VersionControl_RevNumber" at 1035.5,-656.17 h60
  text "SVN REV:" at 1541.5,-656.17 h60
  text ".PCB_Rev" at 2088,-656.17 h60
  text "REV:" at 2379.5,-656.17 h60
  text ".PRJ_Number" at 3224,-656.17 h60
  text "BOARD #:" at 3769.5,-656.17 h60
  text "PCB VIEWED FROM BOTTOM SIDE" at 6246,-656.17 h60
  text ".TID" at 3224,-859.5 h60
  text "TID #:" at 3769.5,-859.5 h60
  text "TEXAS INSTRUMENTS" at 904.5,-1064.84 h60
  text ".Print_Time" at 2169,-1064.84 h60
  text ".Print_Date" at 2898,-1064.84 h60
  text "GENERATED    :" at 3767.5,-1064.84 h60
  text ".plot_File_Name" at 5440.5,-1064.84 h60
  text "PLOT NAME =" at 6246,-1064.84 h60
M9 Title Sheet:
  drawing of 57 lines, arcs and shapes, not listed
  text "1" at 739.84,8036.5 h70
  text "2" at 3235.5,8036.5 h70
  text "3" at 5724.84,8036.5 h70
  text "4" at 8231.51,8036.5 h70
  text "5" at 10730.5,8036.5 h70
  text "6" at 13235.5,8036.5 h70
  text "A" at -416.5,6893.5 h70
  text "A" at 14383.5,6893.5 h70
  text "B" at -416.5,4513.5 h70
  text "B" at 14383.5,4513.5 h70
  text "C" at -416.5,2138.5 h70
  text "C" at 14383.5,2138.5 h70
  text "PROJECT TITLE:" at 11343.5,277.5 h45
  text ".PRJ_Title" at 11393.5,144.17 h70
  text "DESIGNED FOR:" at 11343.5,-23.5 h45
  text ".PRJ_Customer" at 11393.5,-163.5 h70
  text "D" at -416.5,-231.5 h70
  text "D" at 14383.5,-231.5 h70
  text "FILE NAME:" at 11343.5,-323.5 h45
  text ".PCB_File_Name_No_Path" at 11393.5,-443.5 h70
  text "Texas Instruments (TI) and/or its licensors do not warrant the accuracy or completeness of this specification" at 6374,-605.34 h45
  text "ENGINEER:" at 11343.5,-613.5 h45
  text "LAYOUT BY:" at 12848.5,-613.5 h45
  text "or any information contained therein. TI and/or its licensors do not warrant that this design will meet" at 6329.01,-718 h45
  text ".PRJ_Engineer" at 11393.5,-768.49 h70
  text ".PCB_Layout" at 12899,-768.49 h70
  text "the specifications, will be suitable for your application or fit for any particular purpose, or will operate in" at 6329.01,-830.67 h45
  text ".Layer_Name" at 577,-858.49 h60
  text "ALTIUM DESIGNER VERSION:" at 12848.5,-923.5 h45
  text "an implementation. TI and/or its licensors do not warrant that the design is production worthy. You should" at 6329.01,-943.33 h45
  text "completely validate and test your design implementation to confirm the system functionality for your application." at 6374,-1056 h45
  text ".print_Scale" at 11393.5,-1056.83 h70
  text ".Application_BuildNumber" at 12899,-1056.83 h70
  text "1" at 739.84,-1263.5 h70
  text "2" at 3235.5,-1263.5 h70
  text "3" at 5724.84,-1263.5 h70
  text "4" at 8231.51,-1263.5 h70
  text "5" at 10730.5,-1263.5 h70
  text "6" at 13235.5,-1263.5 h70
M10 Fab Notes:
  drawing of 173 lines, arcs and shapes, not listed
  text "DESIGN INFORMATION" at 12377.02,6201 h60
  text "MIN. TRACK WIDTH:" at 11732.46,6021 h60
  text "8" at 12828.7,6021 h60
  text "MIL" at 12983.46,6021 h60
  text "MIN. CLEARANCE:" at 11732.46,5889 h60
  text "0.2" at 12768.7,5889 h60
  text "mm" at 12983.46,5889 h60
  text "MIN. VIA PAD SIZE:" at 11732.46,5757 h60
  text "20" at 12798.71,5757 h60
  text "MIL" at 12983.46,5757 h60
  text "0.05mm (2MIL)" at 12427.46,5615.29 h60
  text "MINIMUM ANNULAR RING" at 11403.23,5611 h60
  text "EXTERNAL" at 13135.46,5611 h60
  text "PER" at 11603.23,5493 h60
  text "IPC-D-275 CLASS 2 LEVEL C" at 11823.23,5493 h60
  text "MIL, HOLES" at 13311.46,5380.71 h60
  text "+/-" at 12919,5380 h60
  text "+/-" at 13773,5380 h60
  text "REGISTRATION TOLERANCES:" at 11403.23,5375 h60
  text "METAL" at 12603,5375 h60
  text "5" at 13179.2,5375 h60
  text "3" at 14012.2,5375 h60
  text "MIL" at 14128.46,5375 h60
  text "+/-" at 13773,5262 h60
  text "HOLE SIZE TOLERANCE (UNLESS OTHERWISE SPECIFIED):" at 11403.23,5257 h60
  text "3" at 14012.2,5257 h60
  text "MIL" at 14128.46,5257 h60
  text "MATERIAL:" at 11328.46,5047.54 h60
  text "FR-4 High Tg" at 12314.9,4907.21 h60
  text "X" at 11600,4905 h60
  text "FR-408" at 11749.46,4898.64 h60
  text "OTHER" at 13237.46,4898.64 h60
  text "62 MIL (1.6mm) +/-10%" at 12069.56,4735.92 h60
  text "THICKNESS:" at 11403.23,4731.64 h60
  text "X" at 11941.4,4731.64 h60
  text "OTHER" at 13354.46,4731.64 h60
  text "TOLERANCE:" at 11403.23,4573.64 h60
  text "X" at 12242.53,4573.64 h60
  text "ANSI IPC-6012 TYPE 3 CLASS 2" at 12429.48,4573.64 h60
  text "OTHER +/-" at 12429.46,4417.64 h60
  text "BOW & TWIST:" at 11403.23,4260.64 h60
  text "X" at 12242.53,4260.64 h60
  text "ANSI IPC-6012 TYPE 3 CLASS 2" at 12429.48,4260.64 h60
  text "OTHER +/-" at 12429.46,4102.13 h60
  text "DRILLING:" at 11328.46,3963.64 h60
  text "REFERENCE:" at 11403.23,3846.64 h60
  text "X" at 12051.46,3846.64 h60
  text "AS SHOWN" at 12238.46,3846.64 h60
  text "X" at 12952.46,3846.64 h60
  text "NC_DRILL FILES" at 13089.46,3846.64 h60
  text "PTH MIN COPPER THICKNESS:" at 11403.23,3688.64 h60
  text "X" at 12753.46,3688.64 h60
  text "1MIL" at 12890.46,3688.64 h60
  text "OTHER" at 13387.46,3688.64 h60
  text "BOARD FINISH:" at 11328.46,3529.64 h60
  text "SILKSCREEN:" at 11483.68,3411.64 h60
  text "X" at 12432.46,3411.64 h60
  text "TOP" at 12558.46,3411.64 h60
  text "X" at 12942.46,3411.64 h60
  text "BOTTOM" at 13069.46,3411.64 h60
  text "SILKSCREEN COLOR:" at 11483.68,3244.64 h60
  text "X" at 12431.42,3244.64 h60
  text "WHITE" at 12558.46,3244.64 h60
  text "OTHER" at 13069.46,3244.64 h60
  text "X" at 12562.42,3085.44 h60
  text "GREEN" at 12689.46,3085.44 h60
  text "OTHER" at 13307.46,3085.44 h60
  text "SOLDER RESIST COLOR:" at 11483.68,3074.64 h60
  text "X" at 12562.42,2915.44 h60
  text "MATTE" at 12689.46,2915.44 h60
  text "SEMI-GLOSS" at 13307,2914.8 h60
  text "IMMERSION GOLD (ENIG)" at 12389.46,2726.92 h60
  text "ENEPIG" at 13727,2723.64 h60
  text "SURFACE FINISH:" at 11328.46,2722.64 h60
  text "IMM. TIN/SILVER OR EQUIV" at 11658,2565.64 h60
  text "OTHER" at 13089.46,2565.64 h60
  text "X" at 11500,2560 h60
  text "ARRAY/PANEL:" at 11328.46,2386.64 h60
  text "CUT AND TRIM PER M1 BOARD OUTLINE" at 12389.46,2382.35 h60
  text "X" at 12210,2380 h60
  text "N.C. ROUTE" at 12389.46,2230.64 h60
  text "V. SCORE" at 13255.46,2230.64 h60
  text "CERTIFICATION:" at 11328.46,2093.64 h60
  text "MATERIALS AND WORKMANSHIP FOR ALL PCBS" at 12053.46,2093.64 h60
  text "TO MEET OR EXCEED THE REQUIREMENTS OF:" at 12053.46,1995.64 h60
  text "X" at 11679.96,1859.13 h60
  text "ANSI IPC-A-600F CLASS ->" at 11818.96,1859.13 h60
  text "X" at 13458.02,1859.13 h60
  text "2" at 13576.96,1859.14 h60
  text "1" at 13261.96,1857.64 h60
  text "3" at 13930.96,1857.64 h60
  text "X" at 12494.02,1699.64 h60
  text "RoHS" at 12630.96,1699.64 h60
  text "OTHER" at 13275.36,1699.64 h60
  text "PER ORDER" at 13672.42,1699.64 h60
  text "ALL BOARDS MUST MEET OR EXCEED UL94-V0 REQUIREMENTS." at 11356,1534 h60
  text "PCB MUST BEAR THE UL94V-0 UL REGISTERED MATERIAL ID NUMBER" at 11356,1414 h60
  text "ADDITIONAL REQUIREMENTS:" at 11328.46,1240.64 h60
  text "MICROSECTION:" at 11403.23,1125.64 h60
  text "YES" at 12308.96,1125.64 h60
  text "X" at 13645,975 h60
  text "REQUIRED" at 13170.46,969.49 h60
  text "BARE BOARD ELEC. TEST:" at 11403.23,966.64 h60
  text "NONE" at 12708.96,966.64 h60
  text "PER ORDER" at 13762.46,966.64 h60
  text ".Layer_Name" at 577,-858.49 h60
M11 Gerber Information:
  lines w10: -292,-930.17 6308,-930.17 ; -292,-726.83 6310,-726.83 ; -292,-523.5 -292,-1133.5 3713,-1133.5 6310,-1133.5 6310,-523.5 -291.5,-523.5 -291.5,-1133.5 1284,-1133.5 ; 2173,-1133.5 2173,-523.5 ; 3440,-726.83 3440,-523.5 ; 4280,-726.83 4280,-523.5 ; 4902,-1140 4902,-937.17
  text "ALL ARTWORK VIEWED FROM TOP SIDE" at -228.5,-655.67 h60
  text "BOARD #:" at 2248,-655.67 h60
  text ".PRJ_Number" at 2793.5,-655.67 h60
  text "REV:" at 3638,-655.67 h60
  text ".PCB_Rev" at 3929.5,-655.67 h60
  text "SVN REV:" at 4476,-655.67 h60
  text ".VersionControl_RevNumber" at 4982,-655.67 h60
  text "LAYER NAME =" at -228.5,-858.49 h60
  text "TID #:" at 2248,-859 h60
  text ".TID" at 2793.5,-859 h60
  text "PLOT NAME =" at -228.5,-1064.34 h60
  text ".plot_File_Name" at 577,-1064.34 h60
  text "GENERATED    :" at 2250,-1064.34 h60
  text ".Print_Date" at 3119.5,-1064.34 h60
  text ".Print_Time" at 3848.5,-1064.34 h60
  text "TEXAS INSTRUMENTS" at 5113,-1064.34 h60
M12 Stackup:
  drawing of 295 lines, arcs and shapes, not listed
  text "Layer" at 6505.58,7445 h60
  text "Name" at 6915.49,7445 h60
  text "Material" at 7855.23,7445 h60
  text "Thickness" at 8715,7445 h60
  text "Constant" at 9364.84,7445 h60
  text "Board Layer Stack" at 9934.7,7445 h60
  text "1" at 6505.58,7325 h60
  text "Top Overlay" at 6915.49,7325 h60
  text "2" at 6505.58,7205 h60
  text "Top Solder" at 6915.49,7205 h60
  text "Solder Resist" at 7855.23,7205 h60
  text "0.40mil" at 8715,7205 h60
  text "3.5" at 9364.84,7205 h60
  text "3" at 6505.58,7085 h60
  text "Top Layer" at 6915.49,7085 h60
  text "Copper" at 7855.23,7085 h60
  text "1.40mil" at 8715,7085 h60
  text "4" at 6505.58,6965 h60
  text "Dielectric1" at 6915.49,6965 h60
  text "FR-4" at 7855.23,6965 h60
  text "20.00mil" at 8715,6965 h60
  text "4.8" at 9364.84,6965 h60
  text "5" at 6505.58,6845 h60
  text "Signal Layer 1" at 6915.49,6845 h60
  text "Copper" at 7855.23,6845 h60
  text "0.70mil" at 8715,6845 h60
  text "6" at 6505.58,6725 h60
  text "Dielectric 2" at 6915.49,6725 h60
  text "17.00mil" at 8715,6725 h60
  text "4.2" at 9364.84,6725 h60
  text "7" at 6505.58,6605 h60
  text "Signal Layer 2" at 6915.49,6605 h60
  text "Copper" at 7855.23,6605 h60
  text "0.70mil" at 8715,6605 h60
  text "8" at 6505.58,6485 h60
  text "Dielectric 3" at 6915.49,6485 h60
  text "FR-4" at 7855.23,6485 h60
  text "20.00mil" at 8715,6485 h60
  text "4.8" at 9364.84,6485 h60
  text "9" at 6505.58,6365 h60
  text "Bottom Layer" at 6915.49,6365 h60
  text "Copper" at 7855.23,6365 h60
  text "1.40mil" at 8715,6365 h60
  text "10" at 6505.58,6245 h60
  text "Bottom Solder" at 6915.49,6245 h60
  text "Solder Resist" at 7855.23,6245 h60
  text "0.40mil" at 8715,6245 h60
  text "3.5" at 9364.84,6245 h60
  text "11" at 6505.58,6125 h60
  text "Bottom Overlay" at 6915.49,6125 h60
  text ".Layer_Name" at 577,-858.49 h60
M13 Component Bodies Top:
  text ".Layer_Name" at 577,-858.49 h60
M14 Component Bodies Bottom:
  text ".Layer_Name" at 577,-858.49 h60
M15 Courtyards Top:
  text ".Layer_Name" at 577,-858.49 h60
M16 Courtyards Bottom:
  text ".Layer_Name" at 577,-858.49 h60
Drill Drawing:
  lines w1: 3047.89,1046.46 3097.71,1046.46 3097.71,1096.28 3047.89,1096.28 3047.89,1046.46 ; 3047.89,1208.38 3060.35,1208.38 3060.35,1195.92 3085.26,1195.92 3085.26,1208.38 3097.71,1208.38 3097.71,1233.28 3085.26,1233.28 3085.26,1245.74 3060.35,1245.74 3060.35,1233.28 3047.89,1233.28 3047.89,1208.38
  lines w12: 2980,1001.62 5099.4,1001.62 ; 2980,1300.54 5099.4,1300.54 ; 3350.67,852.17 3350.67,1450 ; 3707.78,852.17 3707.78,1450 ; 4369.79,852.17 4369.79,1450 ; 4654.14,852.17 4654.14,1450 ; 2980,852.17 5099.4,852.17 5099.4,1450 2980,1450 2980,852.17
  text "Symbol" at 3069.68,1345.38 h72
  text "Quantity" at 3395.51,1345.38 h72
  text "Finished Hole Size" at 3752.62,1345.38 h72
  text "Plated" at 4414.62,1345.38 h72
  text "Hole Type" at 4698.98,1345.38 h72
  text "60" at 3395.51,1195.92 h60
  text "10.00mil (0.254mm)" at 3752.62,1195.92 h60
  text "PTH" at 4414.62,1195.92 h60
  text "Round" at 4698.98,1195.92 h60
  text "1" at 3395.51,1046.46 h60
  text "28.00mil (0.711mm)" at 3752.62,1046.46 h60
  text "PTH" at 4414.62,1046.46 h60
  text "Round" at 4698.98,1046.46 h60
  text "61 Total" at 3395.51,897 h60
  text ".Layer_Name" at 577,-858.49 h60

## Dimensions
0,-400 to 1000,-400 on M2 Board Dimensions
0,0 to 0,1300 on M2 Board Dimensions
0,0 to 1580,0 on M2 Board Dimensions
